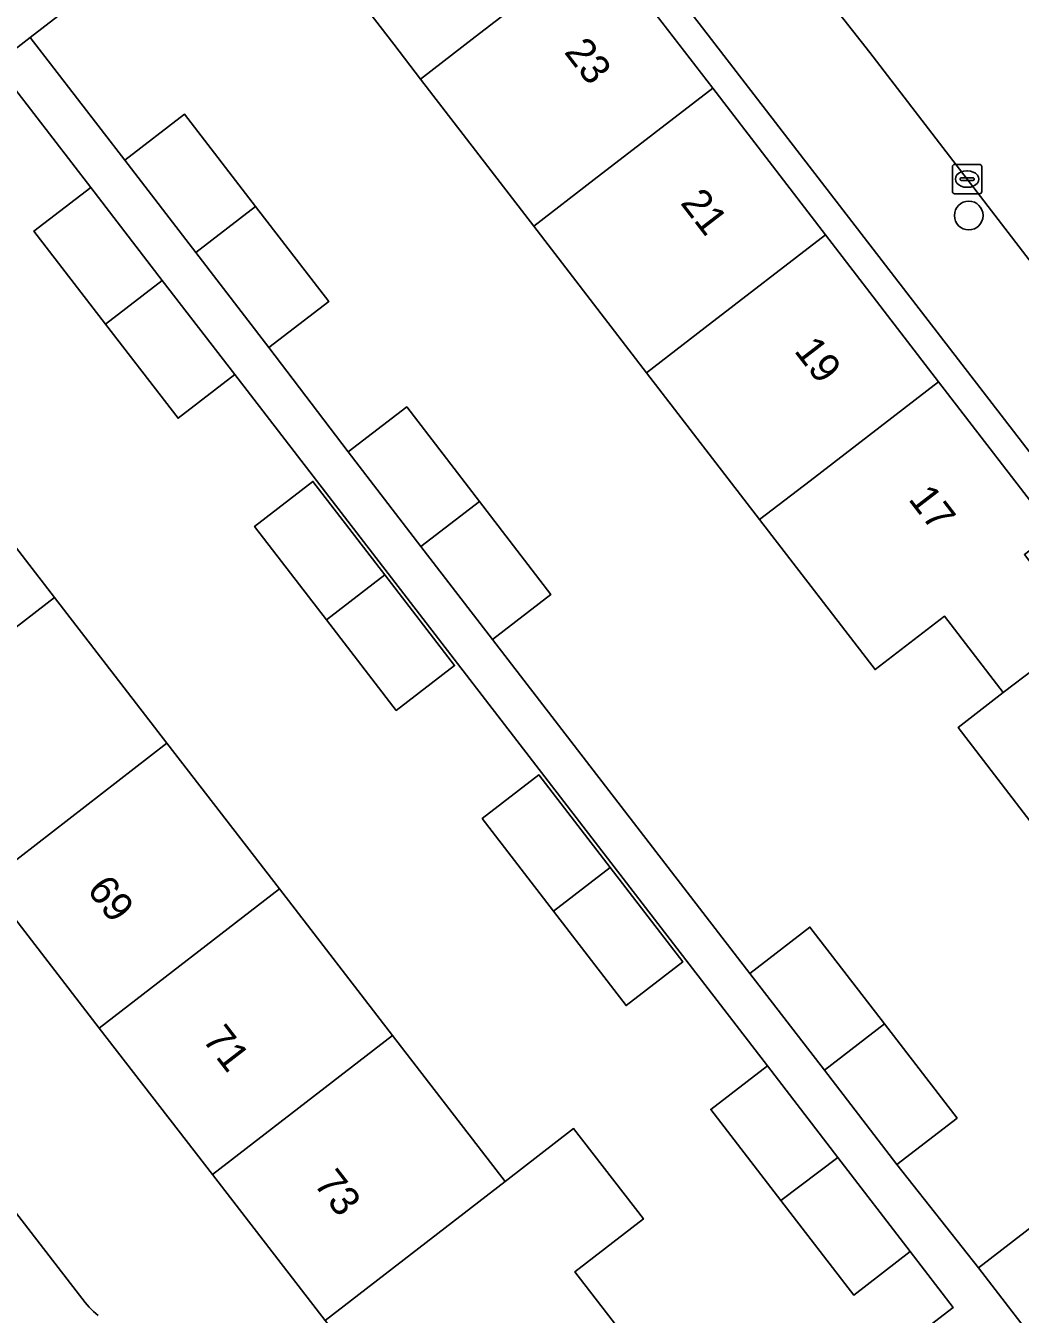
# Model space of a CAD drawing. Extents: x 159217 to 160349, y 381246 to 382172.
# Drawn here: x 159691.35 to 159725.23, y 381509.61 to 381553.5 of the extents above; entities that cross this region are included whole.
import ezdxf

# ---------------------------------------------------------------- set-up
doc = ezdxf.new("R2010")
doc.units = 0
for name, color, linetype in [('IMGEO_Boom', 7, 'Continuous'), ('IMGEO_Erf', 7, 'Continuous'), ('IMGEO_Kolk', 7, 'Continuous'), ('IMGEO_Pand', 7, 'Continuous'), ('IMGEO_Pand_nummerreeks', 7, 'Continuous'), ('IMGEO_Parkeervlak_open', 7, 'Continuous'), ('IMGEO_Rijbaan_lokaal_gesloten', 7, 'Continuous'), ('IMGEO_Voetpad_open', 7, 'Continuous')]:
    doc.layers.add(name, color=color, linetype=linetype)

msp = doc.modelspace()

# ---------------------------------------------------------------- linework, layer by layer
at = {"layer": 'IMGEO_Boom'}
msp.add_circle((159723.476, 381547.034), 0.489, dxfattribs=at)
at = {"layer": 'IMGEO_Erf'}
for points in [[(159704.352, 381563.016), (159691.497, 381553.096), (159694.72, 381548.92), (159696.755, 381550.488), (159699.173, 381547.347), (159701.669, 381544.105), (159699.634, 381542.538), (159702.33, 381538.982), (159704.326, 381540.518), (159706.805, 381537.297), (159709.242, 381534.132), (159707.246, 381532.595), (159716.017, 381521.225), (159718.067, 381522.802), (159720.606, 381519.503), (159723.077, 381516.293), (159721.028, 381514.716), (159723.808, 381511.2), (159725.798, 381512.732)], [(159727.181, 381536.865), (159707.443, 381562.46)], [(159727.061, 381524.467), (159723.113, 381529.596), (159724.651, 381530.79), (159722.649, 381533.39), (159720.285, 381531.57), (159716.351, 381536.679), (159712.5, 381541.681), (159708.656, 381546.673), (159704.8, 381551.682), (159703.888, 381552.866), (159700.838, 381556.828), (159706.936, 381561.522), (159710.897, 381556.378), (159714.753, 381551.369), (159718.598, 381546.376), (159722.448, 381541.375), (159726.383, 381536.264)], [(159719.854, 381507.468), (159722.946, 381509.848), (159721.481, 381511.75), (159719.555, 381510.267), (159717.076, 381513.487), (159714.688, 381516.589), (159716.614, 381518.072), (159698.469, 381541.618), (159696.536, 381540.13), (159694.069, 381543.333), (159691.628, 381546.503), (159693.561, 381547.992), (159690.322, 381552.189), (159671.829, 381537.917), (159693.37, 381510.017), (159693.505, 381509.857), (159693.654, 381509.709), (159693.816, 381509.575)], [(159701.545, 381509.399), (159697.706, 381514.37), (159693.854, 381519.357), (159690.02, 381524.321), (159686.187, 381529.284), (159682.335, 381534.273), (159678.385, 381539.387), (159684.526, 381544.128), (159688.475, 381539.014), (159692.326, 381534.026), (159696.158, 381529.062), (159699.991, 381524.098), (159703.843, 381519.109), (159707.681, 381514.138), (159710.015, 381515.94), (159712.39, 381512.863), (159710.056, 381511.061), (159711.52, 381509.165)]]:
    msp.add_lwpolyline(points, dxfattribs=at)
for points in [[(159701.131, 381537.978), (159703.58, 381534.795), (159705.957, 381531.707), (159703.971, 381530.178), (159701.596, 381533.263), (159699.144, 381536.448)], [(159709.325, 381523.342), (159706.899, 381526.493), (159708.833, 381527.981), (159711.256, 381524.834), (159713.734, 381521.615), (159711.8, 381520.126)]]:
    msp.add_lwpolyline(points, close=True, dxfattribs=at)
at = {"layer": 'IMGEO_Kolk'}
for p, q in [((159722.92, 381547.849), (159722.92, 381548.701)), ((159722.995, 381548.775), (159723.847, 381548.775)), ((159723.921, 381548.701), (159723.921, 381547.849)), ((159723.179, 381548.269), (159723.179, 381548.281)), ((159723.617, 381548.232), (159723.219, 381548.232)), ((159723.222, 381548.318), (159723.62, 381548.318)), ((159723.408, 381548.555), (159723.433, 381548.555)), ((159723.663, 381548.281), (159723.663, 381548.269)), ((159723.431, 381547.995), (159723.406, 381547.995)), ((159723.847, 381547.775), (159722.995, 381547.775))]:
    msp.add_line(p, q, dxfattribs=at)
for points in [[(159722.92, 381547.849), (159722.92, 381548.701)], [(159722.995, 381548.775), (159723.847, 381548.775)], [(159723.921, 381548.701), (159723.921, 381547.849)], [(159723.847, 381547.775), (159722.995, 381547.775)]]:
    msp.add_lwpolyline(points, dxfattribs=at)
for centre, radius, start, end in [((159722.997, 381548.699), 0.0765, 91.552, 178.448), ((159722.997, 381548.699), 0.0765, 91.552, 178.448), ((159723.845, 381548.699), 0.0765, 1.552, 88.448), ((159723.845, 381548.699), 0.0765, 1.552, 88.448), ((159723.219, 381548.278), 0.0403, 85.8775, 175.7526), ((159723.216, 381548.268), 0.0366, 178.938, 274.7102), ((159723.62, 381548.275), 0.043, 264.8664, 352.4533), ((159723.624, 381548.28), 0.0386, 1.7309, 96.639), ((159722.997, 381547.851), 0.0765, 181.552, 268.448), ((159722.997, 381547.851), 0.0765, 181.552, 268.448), ((159723.845, 381547.851), 0.0765, 271.552, 358.448), ((159723.845, 381547.851), 0.0765, 271.552, 358.448)]:
    msp.add_arc(centre, radius, start, end, dxfattribs=at)
for centre, major_axis, ratio, start_param, end_param in [((159723.407, 381548.275), (-0.387, 0.002), 0.722429, 4.712389, 7.853982), ((159723.432, 381548.275), (-0.39, 0.002), 0.717154, 1.570796, 4.712389)]:
    msp.add_ellipse(centre, major_axis=major_axis, ratio=ratio, start_param=start_param, end_param=end_param, dxfattribs=at)
at = {"layer": 'IMGEO_Pand'}
for points in [[(159704.8, 381551.682), (159706.662, 381553.116), (159710.897, 381556.378), (159706.936, 381561.522), (159700.838, 381556.828), (159703.888, 381552.866)], [(159714.753, 381551.369), (159710.897, 381556.378), (159706.662, 381553.116), (159704.8, 381551.682), (159708.656, 381546.673), (159710.712, 381548.257)], [(159714.753, 381551.369), (159710.712, 381548.257), (159708.656, 381546.673), (159712.5, 381541.681), (159714.494, 381543.216), (159718.598, 381546.376)], [(159699.173, 381547.347), (159696.755, 381550.488), (159694.72, 381548.92), (159697.138, 381545.78)], [(159696, 381544.824), (159693.561, 381547.992), (159691.628, 381546.503), (159694.069, 381543.333)], [(159699.173, 381547.347), (159697.138, 381545.78), (159699.634, 381542.538), (159701.669, 381544.105)], [(159722.448, 381541.375), (159718.598, 381546.376), (159714.494, 381543.216), (159712.5, 381541.681), (159716.351, 381536.679), (159718.069, 381538.002)], [(159696, 381544.824), (159694.069, 381543.333), (159696.536, 381540.13), (159698.469, 381541.618)], [(159722.448, 381541.375), (159718.069, 381538.002), (159716.351, 381536.679), (159720.285, 381531.57), (159722.649, 381533.39), (159724.651, 381530.79), (159725.724, 381531.609), (159727.376, 381532.881), (159725.371, 381535.485), (159726.383, 381536.264)], [(159702.33, 381538.982), (159704.809, 381535.761), (159706.805, 381537.297), (159704.326, 381540.518)], [(159686.187, 381529.284), (159692.326, 381534.026), (159688.475, 381539.014), (159682.335, 381534.273)], [(159701.596, 381533.263), (159703.58, 381534.795), (159701.131, 381537.978), (159699.144, 381536.448)], [(159706.805, 381537.297), (159704.809, 381535.761), (159707.246, 381532.595), (159709.242, 381534.132)], [(159703.58, 381534.795), (159701.596, 381533.263), (159703.971, 381530.178), (159705.957, 381531.707)], [(159727.061, 381524.467), (159733.181, 381529.174), (159729.233, 381534.307), (159727.376, 381532.881), (159725.724, 381531.609), (159724.651, 381530.79), (159723.113, 381529.596)], [(159686.187, 381529.284), (159690.02, 381524.321), (159696.158, 381529.062), (159692.326, 381534.026)], [(159699.991, 381524.098), (159696.158, 381529.062), (159690.02, 381524.321), (159693.854, 381519.357)], [(159709.325, 381523.342), (159711.256, 381524.834), (159708.833, 381527.981), (159706.899, 381526.493)], [(159711.256, 381524.834), (159709.325, 381523.342), (159711.8, 381520.126), (159713.734, 381521.615)], [(159699.991, 381524.098), (159693.854, 381519.357), (159697.706, 381514.37), (159703.843, 381519.109)], [(159716.017, 381521.225), (159718.556, 381517.926), (159720.606, 381519.503), (159718.067, 381522.802)], [(159720.606, 381519.503), (159718.556, 381517.926), (159721.028, 381514.716), (159723.077, 381516.293)], [(159701.545, 381509.399), (159707.681, 381514.138), (159703.843, 381519.109), (159697.706, 381514.37)], [(159719.016, 381514.953), (159716.614, 381518.072), (159714.688, 381516.589), (159717.076, 381513.487)], [(159710.056, 381511.061), (159712.39, 381512.863), (159710.015, 381515.94), (159707.681, 381514.138), (159701.545, 381509.399), (159705.384, 381504.427), (159711.52, 381509.165)], [(159721.481, 381511.75), (159719.016, 381514.953), (159717.076, 381513.487), (159719.555, 381510.267)], [(159726.274, 381507.996), (159728.265, 381509.527), (159725.798, 381512.732), (159723.808, 381511.2)]]:
    msp.add_lwpolyline(points, close=True, dxfattribs=at)
at = {"layer": 'IMGEO_Parkeervlak_open'}
msp.add_lwpolyline([(159690.322, 381552.189), (159691.497, 381553.096), (159704.352, 381563.016)], dxfattribs=at)
at = {"layer": 'IMGEO_Rijbaan_lokaal_gesloten'}
msp.add_lwpolyline([(159711.418, 381563.617), (159720.102, 381552.591), (159728.968, 381541.067)], dxfattribs=at)
at = {"layer": 'IMGEO_Voetpad_open'}
for points in [[(159728.968, 381541.067), (159720.102, 381552.591), (159711.418, 381563.617), (159710.036, 381565.36), (159709.042, 381566.641), (159704.352, 381563.016), (159704.376, 381563.032), (159704.545, 381563.135), (159704.722, 381563.222), (159704.907, 381563.292), (159705.097, 381563.346), (159705.291, 381563.383), (159705.488, 381563.402), (159705.685, 381563.404), (159705.882, 381563.388), (159706.013, 381563.352), (159706.282, 381563.259), (159706.541, 381563.142), (159706.788, 381563.002), (159707.022, 381562.841), (159707.241, 381562.66), (159707.443, 381562.46), (159727.181, 381536.865)], [(159726.274, 381507.996), (159723.808, 381511.2), (159721.028, 381514.716), (159718.556, 381517.926), (159716.017, 381521.225), (159707.246, 381532.595), (159704.809, 381535.761), (159702.33, 381538.982), (159699.634, 381542.538), (159697.138, 381545.78), (159694.72, 381548.92), (159691.497, 381553.096), (159690.322, 381552.189), (159693.561, 381547.992), (159696, 381544.824), (159698.469, 381541.618), (159716.614, 381518.072), (159719.016, 381514.953), (159721.481, 381511.75), (159722.946, 381509.848), (159719.854, 381507.468)], [(159693.816, 381509.575), (159693.654, 381509.709), (159693.505, 381509.857), (159693.37, 381510.017), (159671.829, 381537.917), (159669.416, 381536.026), (159672.284, 381532.256), (159682.363, 381519.388), (159686.939, 381513.347), (159691.162, 381507.857)]]:
    msp.add_lwpolyline(points, dxfattribs=at)

# ---------------------------------------------------------------- texts
at = {"layer": 'IMGEO_Pand_nummerreeks'}
for s, rotation, p in [('23', 307.5939, (159709.667, 381552.597)), ('21', 307.5939, (159713.626, 381547.457)), ('19', 307.5939, (159717.502, 381542.422)), ('17', 307.5939, (159721.391, 381537.371)), ('69', 307.6785, (159693.403, 381524.063)), ('71', 307.6785, (159697.338, 381518.968)), ('73', 307.6785, (159701.134, 381514.053))]:
    msp.add_text(s, height=1, rotation=rotation, dxfattribs=at).set_placement(p)

doc.saveas('drawing.dxf')
